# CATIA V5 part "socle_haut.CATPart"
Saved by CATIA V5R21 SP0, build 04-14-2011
Part number: socle_haut
Revision: A
Nomenclature: 4
Material "Blanc": density 7860 kg/m3, Young's modulus 2e+11 Pa, Poisson ratio 0.266
Bounding box of the stored display mesh (mm): x -22 to 22, y -70 to 42.5, z 0 to 62
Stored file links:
  C:\Users\Olivier\Desktop\redaction CATIA (local)\CATIA\DONNEES\Exercice assemblage 3 (Pompe de ventilation)\socle_haut.CATPart
  C:\Program Files\Dassault Systemes\B21\win_b64\startup\materials\French\Catalog.CATMaterial
  C:\Users\Olivier\Desktop\redaction CATIA (local)\pompe à moteur de ventilation refait\Pompe_a_moteur_de_ventilation.CATProduct
  C:\Users\Olivier\Desktop\redaction CATIA (local)\pompe à moteur de ventilation refait\Ecrou a collerette M5.CATPart
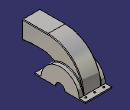
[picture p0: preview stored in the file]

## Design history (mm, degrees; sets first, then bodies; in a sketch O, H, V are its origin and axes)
Body1 (main body), material "Blanc"
  Sketch1 on yz-plane, origin (0, 0, 0), H (0, 1, 0), V (0, 0, 1)
    arc A1 centre (0, 0) radius 8 from (8, 0) to (-8, 0) ccw
    arc A2 centre (0, 0) radius 32 from (-16, 27.7128) to (-31.9374, 2) ccw
    point P1 (-42.5, 0)
    line L1 (-42.5, 0) -> (-8, 0)
    line L2 (42.5, 0) -> (42.5, 2)
    line L3 (42.5, 2) -> (32, 2)
    line L4 (-42.5, 2) -> (-42.5, 0)
    point P3 (42.5, 2)
    point P4 (-42.5, 2)
    point P6 (8, 0)
    line L5 (8, 0) -> (42.5, 0)
    line L6 (-31.9374, 2) -> (-42.5, 2)
    point P8 (32, 2)
    arc A3 centre (-28, 2) radius 60 from (32, 2) to (-28, 62) ccw
    line L7 (-28, 62) -> (-70, 62)
    point P11 (-70, 62)
    construction line L8 (0, 0) -> (-16, 27.7128)
    point P12 (-16, 27.7128)
    line L9 (-16, 27.7128) -> (-24.137, 31.367)
    point P13 (-16, 27.7128)
    point P14 (-30, 34)
    line L10 (-36.4271, 34) -> (-53.0088, 34)
    point P15 (-55, 34)
    line L11 (-56.9737, 33.7368) -> (-70, 32)
    point P16 (-70, 32)
    line L12 (-70, 32) -> (-70, 62)
    construction line L13 (32, 2) -> (32, 18.4391)
    arc A4 centre (0.0604, 0.035) radius 32 from (-16, 27.7128) to (32, 2) cw
    point P19 (-16, 27.7128)
    arc A5 centre (-53.0088, 4) radius 30 from (-53.0088, 34) to (-56.9737, 33.7368) ccw
    arc A6 centre (-36.4271, 4) radius 30 from (-24.137, 31.367) to (-36.4271, 34) ccw
    radius A1 = 8
    radius A2 = 32
    length L2 = 2
    distance P3 P4 = 85
    radius A3 = 60
    distance P11 V = 70
    distance P16 P11 = 30
    distance L10 L7 = 28
    distance P14 P16 H = 40
    angle L8 V = 30
    distance P8 V = 32
    radius A4 = 32
    distance P15 P16 H = 15
    radius A5 = 30
    radius A6 = 30
    coincidence: P1 H, L1 P6, L1 L5, L3 L6, P13 A2, P13 P12, A4 P19, P19 A2, L10 P15, L11 P15, L9 P14, L10 P14
    horizontal: L1 H, L3 H, L5 H, L6 H, L7 H, L10 H
    vertical: L2 V, L4 V, L12 V, L13 V
    symmetry: L2 L4 V
    tangency: A3 L7, L13 A3, A5 L10, A5 L11, A6 L9, A6 L10
  MultiPad1: profile Sketch1, domains (length 15 / length 15; length 22 / length 22)
  Sketch2 on yz-plane, origin (0, 0, 0), H (0, 1, 0), V (0, 0, 1)
    circle A1 centre (0, 0) radius 31
    radius A1 = 31
  Pocket1: profile Sketch2, direction (-1, 0, 0), length 21, mirrored extent
  Shell1: ExtOffset 0, Face (face of MultiPad1 from Sketch1.L12; face of Pocket1 from Sketch2.A1), IntOffset 1
  Sketch3 on face of MultiPad1 from Sketch1.L1, origin (12.1493, -36.3201, 0), H (1, 0, 0), V (0, -1, 0)
    point P1 (2.8507, -0.3201)
    reference projected line E1 through (0, -36.3201) direction (1, 0) from axis of face of Pocket1 from Sketch2.A1
    reference intersected line E2 through (-12.1493, 0) direction (0, 1) from yz-plane
    distance P1 E1 = 36
    distance P1 E2 = 15
  Hole1: placed by Sketch3, at (15, -36, 0) direction (0, 0, 1), diameter 3, through (limit type 6)
  RectPattern1: of Hole1, direction 1 instances 3, spacing 15, along edge [face of MultiPad1 from Sketch1.L1 | face of MultiPad1 from Sketch1.L4] reversed, direction 2 instances 2, spacing 72, along edge [face of MultiPad1 from Sketch1.L1 | face of MultiPad1]
  Fillet1: radius 1, on edge [face of MultiPad1 | face of MultiPad1 from Sketch1.L7]; edge [face of MultiPad1 from Sketch1.L7 | face of MultiPad1]; edge [face of MultiPad1 from Sketch1.L11 | face of MultiPad1]; edge [face of MultiPad1 | face of MultiPad1 from Sketch1.L9]; edge [face of MultiPad1 | face of MultiPad1 from Sketch1.A4]; edge [face of MultiPad1 from Sketch1.A2 | face of MultiPad1 from Sketch1.L9]; edge [face of MultiPad1 from Sketch1.A4 | face of MultiPad1]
